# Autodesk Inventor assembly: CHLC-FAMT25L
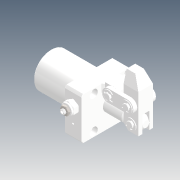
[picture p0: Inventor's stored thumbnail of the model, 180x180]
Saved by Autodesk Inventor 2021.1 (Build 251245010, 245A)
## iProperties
Created: 2019-04
Part Number: CHLC-FAMT25L
Description: STEP AP214
Document SubType Name: Assembly
Designer: user
Title: CHLC-FAMT25L.STEP
Revision Number: ÈÎºÎ
Sending System: SolidWorks 2016
Preprocessor: SwSTEP 2.0
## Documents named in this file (11)
- D:\Vault_2016\Projekty\Clamptek\Hydraulic\CHLC\CHLC-25\Inventor\CHLC-FAMT25L\CHLC-FAMT25L.iam
- D:\Vault_2016\Projekty\Clamptek\Hydraulic\CHLC\CHLC-25\Inventor\CHLC-FAMT25L\CHLC-FAMT25BT.ipt
- D:\Vault_2016\Projekty\Clamptek\Hydraulic\CHLC\CHLC-25\Inventor\CHLC-FAMT25L\CHLC-25CX.ipt
- D:\Vault_2016\Projekty\Clamptek\Hydraulic\CHLC\CHLC-25\Inventor\CHLC-FAMT25L\CHLC-25DX.ipt
- D:\Vault_2016\Projekty\Clamptek\Hydraulic\CHLC\CHLC-25\Inventor\CHLC-FAMT25L\CHLC-25HSG.ipt
- D:\Vault_2016\Projekty\Clamptek\Hydraulic\CHLC\CHLC-25\Inventor\CHLC-FAMT25L\CHLC-25KKDC.ipt
- D:\Vault_2016\Projekty\Clamptek\Hydraulic\CHLC\CHLC-25\Inventor\CHLC-FAMT25L\CHLC-25LG.ipt
- D:\Vault_2016\Projekty\Clamptek\Hydraulic\CHLC\CHLC-25\Inventor\CHLC-FAMT25L\CHLC-25ZC.ipt
- D:\Vault_2016\Projekty\Clamptek\Hydraulic\CHLC\CHLC-25\Inventor\CHLC-FAMT25L\CZL10µ÷ËÙ·§.ipt
- D:\Vault_2016\Projekty\Clamptek\Hydraulic\CHLC\CHLC-25\Inventor\CHLC-FAMT25L\CHLC-25ZC-HAN.ipt
- D:\Vault_2016\Projekty\Clamptek\Hydraulic\CHLC\CHLC-25\Inventor\CHLC-FAMT25L\Ñ¹±Û.ipt
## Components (17 placed, 17 different names)
1. CHLC-FAMT25BT_1
2. CHLC-25CX_2
3. CHLC-25DX_3
4. CHLC-25HSG_4
5. CHLC-25KKDC_5
6. CHLC-25LG_6
7. CHLC-25ZC_7
8. CZL10µ÷ËÙ·§_8
9. CHLC-25LG_9
10. CHLC-25KKDC_10
11. CHLC-25KKDC_11
12. CHLC-25KKDC_12
13. CHLC-25KKDC_13
14. CHLC-25KKDC_14
15. CHLC-25CX_15
16. CHLC-25ZC-HAN_16
17. Ñ¹±Û_17
